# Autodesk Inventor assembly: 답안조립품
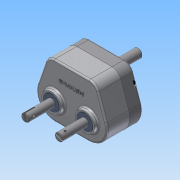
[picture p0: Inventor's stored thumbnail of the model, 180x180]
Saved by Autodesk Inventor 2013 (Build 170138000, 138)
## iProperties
Created: 2014-12
Part Number: 답안조립품
Document SubType Name: Assembly
Designer: kb543-18
Author: kb543-18
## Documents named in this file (14)
- C:\Users\kb543-18\Desktop\441208V1040\답안조립품.iam
- C:\Users\kb543-18\Desktop\441208V1040\본체.ipt
- C:\Users\kb543-18\Desktop\441208V1040\M 5 x 35.ipt
- C:\Users\kb543-18\Desktop\441208V1040\멈춤링.ipt
- C:\Users\kb543-18\Desktop\441208V1040\메인기어.ipt
- C:\Users\kb543-18\Desktop\441208V1040\메인축.ipt
- C:\Users\kb543-18\Desktop\441208V1040\베어링- 6202.ipt
- C:\Users\kb543-18\Desktop\441208V1040\베어링- 6203.ipt
- C:\Users\kb543-18\Desktop\441208V1040\서브기어.ipt
- C:\Users\kb543-18\Desktop\441208V1040\서브축.ipt
- C:\Users\kb543-18\Desktop\441208V1040\오일시일-D-15.ipt
- C:\Users\kb543-18\Desktop\441208V1040\오일시일-D-17.ipt
- C:\Users\kb543-18\Desktop\441208V1040\커버.ipt
- C:\Users\kb543-18\Desktop\441208V1040\키5x5.ipt
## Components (15 placed, 6 different names)
1. KS B 1003 - 미터 M 5 x 35:1
2. KS B 1336 17 x 1:1
3. KS B 2023 6202 - 15 x 35 x 11:1
4. KS B 2023 6203 - 17 x 40 x 12:1
5. KS B 2804 D D - 15 30 7:1
6. KS B 2804 D D - 17 30 8:1
7. KS B 2023 6203 - 17 x 40 x 12:2
8. KS B 2023 6203 - 17 x 40 x 12:3
9. KS B 2023 6203 - 17 x 40 x 12:4
10. KS B 2023 6202 - 15 x 35 x 11:2
11. KS B 1336 17 x 1:2
12. KS B 1336 17 x 1:3
13. KS B 2804 D D - 15 30 7:2
14. KS B 1003 - 미터 M 5 x 35:2
15. KS B 1003 - 미터 M 5 x 35:3
